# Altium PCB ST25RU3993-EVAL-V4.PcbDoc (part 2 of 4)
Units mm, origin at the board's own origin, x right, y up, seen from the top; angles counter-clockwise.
Board outline 76.25 x 96.25 mm, 6 copper layers (Top Layer, RF GND, Power, GND, Routing, Bottom GND), stack 1.022 mm thick; 319 components, 214 nets, 994 pads, 1429 vias.
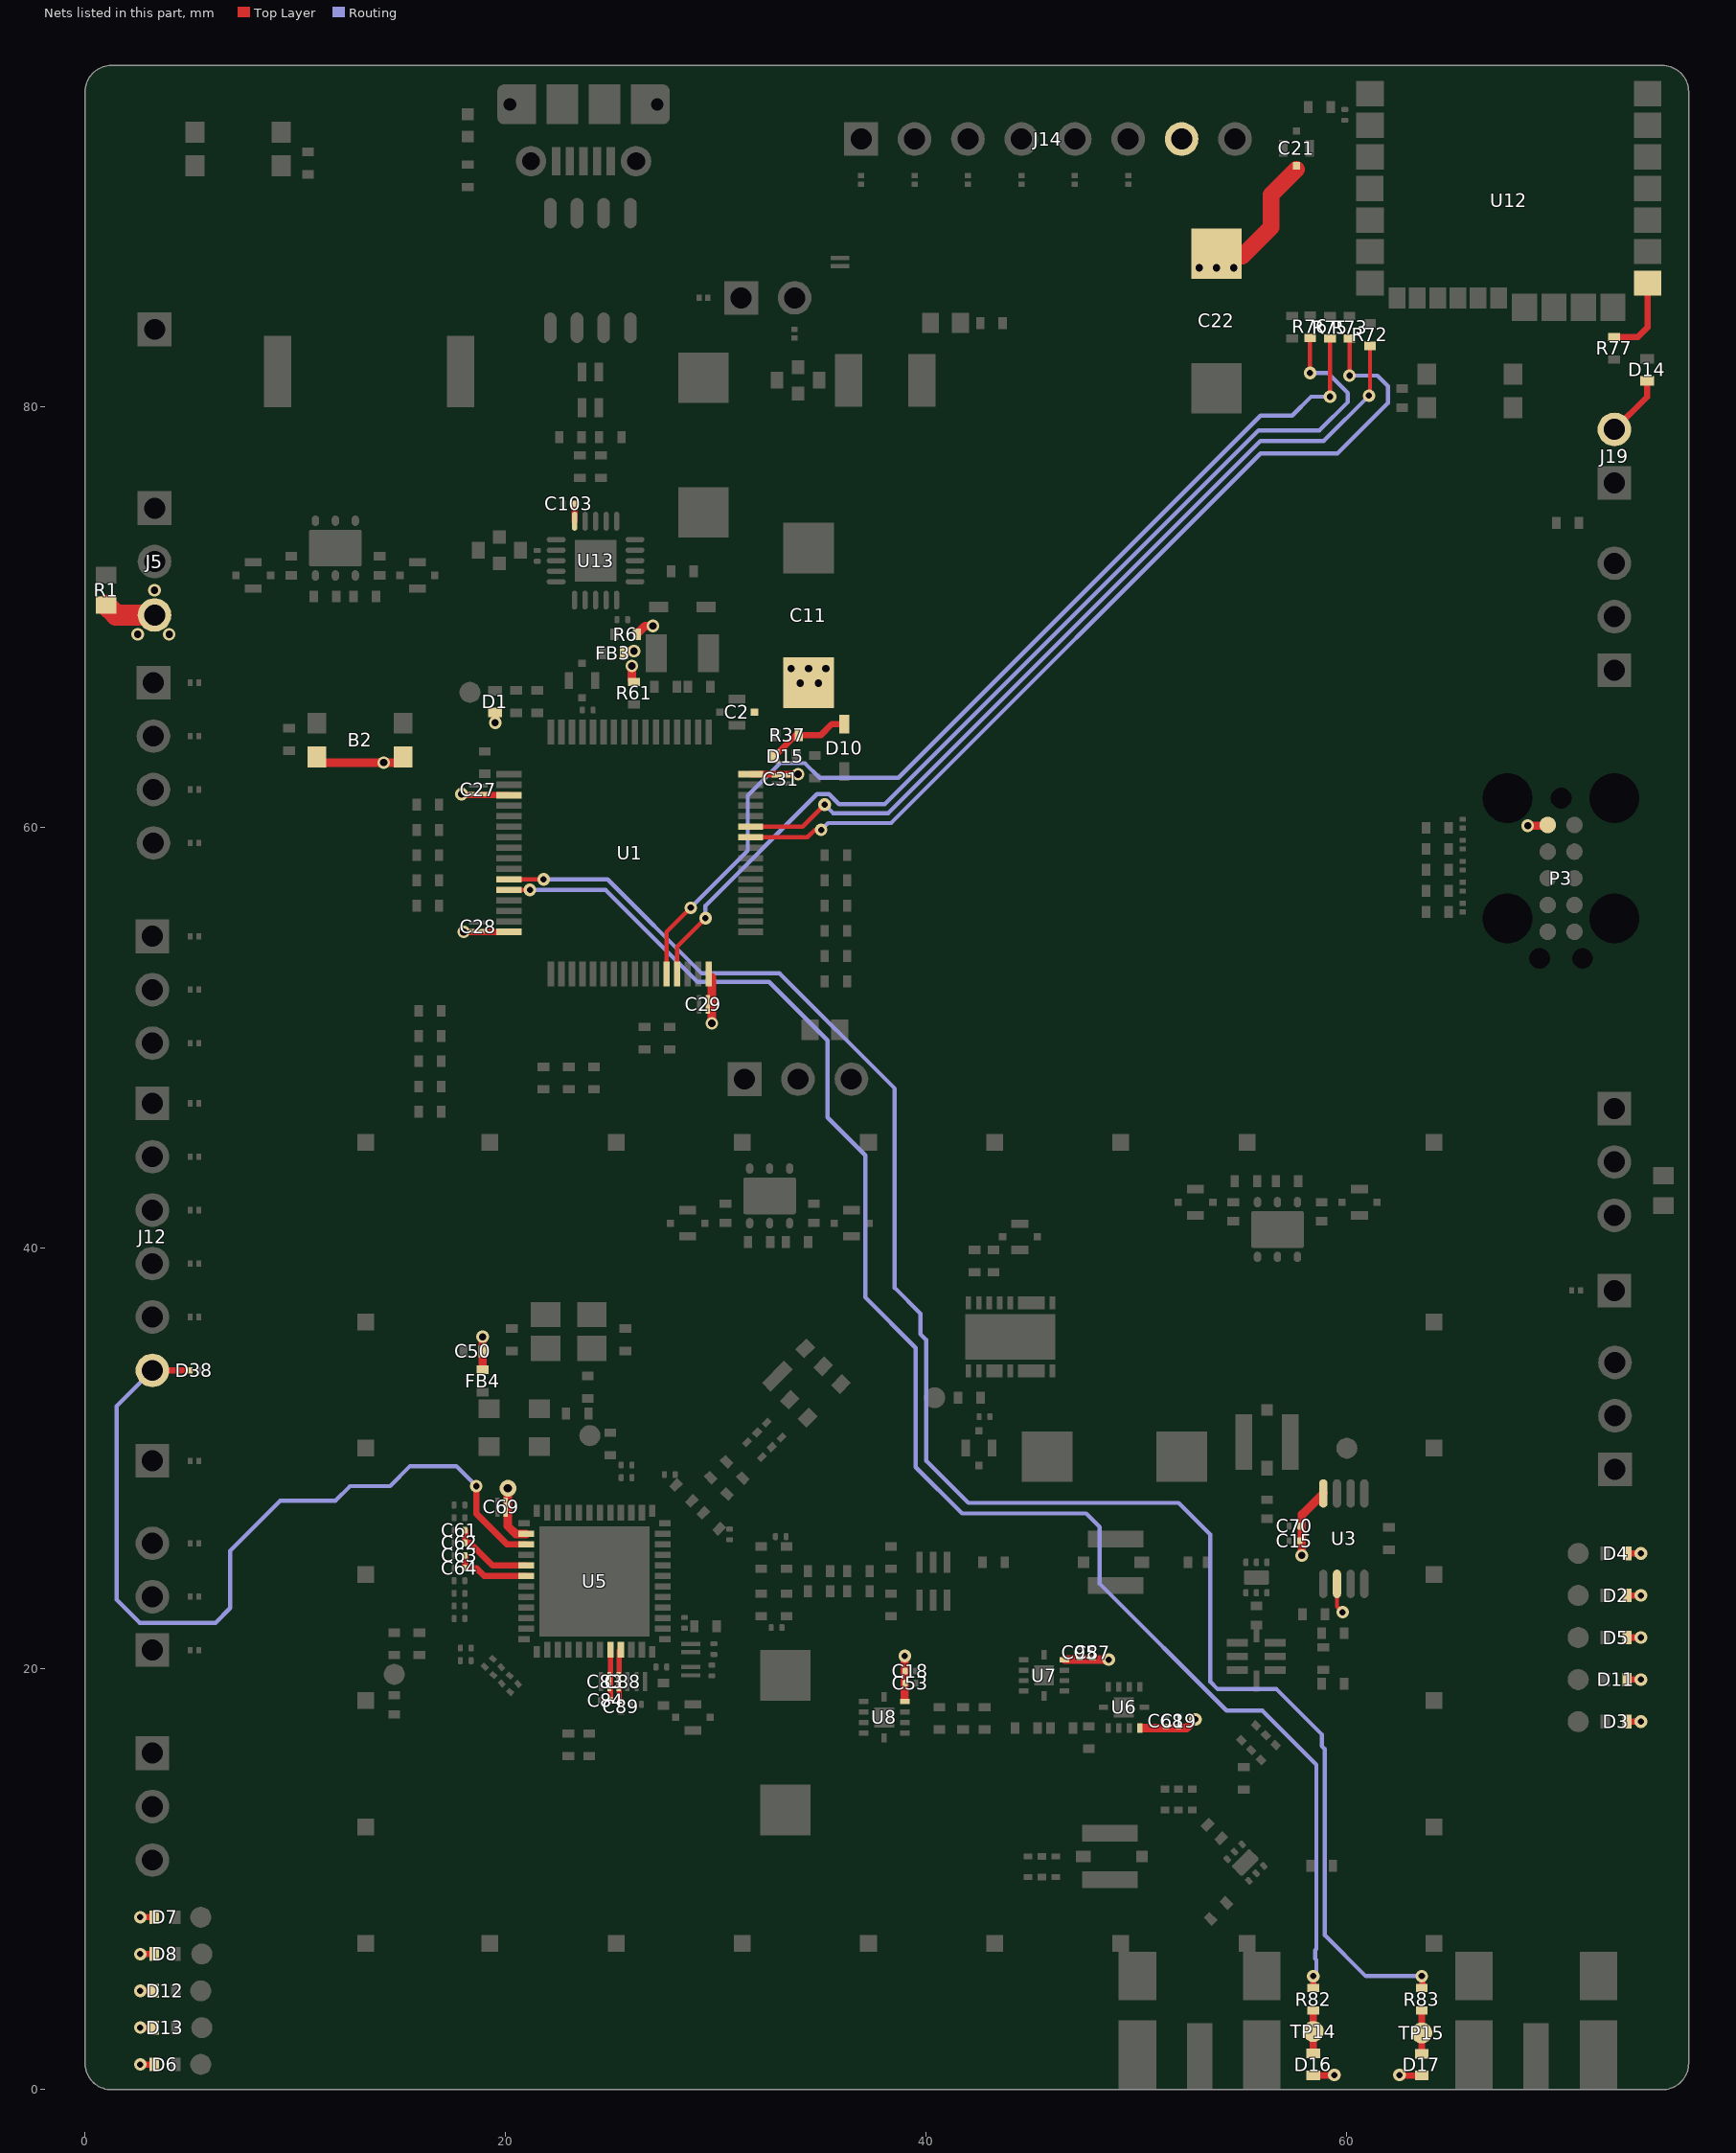
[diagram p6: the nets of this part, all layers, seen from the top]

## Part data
B1 B2 B3: library part SW-PUSH-CMS_BLACK_1, "Non-Open Push-Button 0.1A 24V", Contact Rating @ Voltage="0.05A @ 32VDC", Illumination Type, Color=-, Manufacturer="C&K Components", Manufacturer Part Number="KMR211NG LFS", Operating Force=120gf, Operating Temperature="-40°C ~ 85°C", Supplier Part Number 1=CKN10243DKR-ND
BZ1: library part PKMCS0909E4000-R1, "AUDIO PIEZO TRANSDUCER 12.5V SMD", Current - Supply=-, Frequency=4kHz, Manufacturer="Murata Electronics North America", Operating Mode="Single Tone", Operating Temperature="-40°C ~ 85°C", Supplier Part Number 1=490-9647-1-ND, Voltage - Rated=1.5V, Voltage Range="12.5V (Max)"
C1 C3: library part GRM1555C1H1R2WA01D, "CAP CER 1.2PF 50V NP0 0402", Capacitance=1.2pF, Manufacturer="Murata Electronics North America", Operating Temperature="-55°C ~ 125°C", Package / Case="0402 (1005 Metric)", Ratings=-, Supplier Part Number 1=490-6210-1-ND, Temperature Coefficient="C0G, NP0", Tolerance=±0.05pF, Voltage - Rated=50V
C2 C8 C16 C21 C39 C41 C43 C45 C47 C49 C91 C104: library part NFM18PS474R0J3D, "CAP FEEDTHRU 0.47UF 6.3V 0603", Capacitance=0.47µF, Current=2A, DC Resistance (DCR) (Max)="30 mOhm", ESR (Equivalent Series Resistance)="70 mOhm", Lifetime @ Temp.="1000 Hrs @ 105°C", Manufacturer="Murata Electronics North America", Operating Temperature="-55°C ~ 125°C", Package / Case="0603 (1608 Metric), 3 PC Pad", Ratings=-, Ripple Current - High Frequency="1A @ 100kHz", Supplier Part Number 1=490-6975-1-ND, Tolerance=±20%, Voltage - Rated=6.3V
C4 C5: library part GRM1555C1H150GA01D, "CAP CER 15PF 50V NP0 0402", Manufacturer="Murata Electronics North America", Operating Temperature="-55°C ~ 125°C", Package / Case="0402 (1005 Metric)", Ratings=-, Supplier Part Number 1=490-6201-1-ND, Temperature Coefficient="C0G, NP0", Tolerance=±2%, Voltage - Rated=50V
C6 C7: library part GJM1555C1H5R6CB01D, "CAP CER 5.6PF 50V NP0 0402", Capacitance=5.6pF, Frequency Max=960, Frequency Min=380, Frequency Range="380MHz to 960", Manufacturer="Murata Electronics North America", Manufacturer 2=RFMD, Manufacturer Part Number 2=RFPA0133, Operating Temperature="-55°C ~ 125°C", Operating Temperature Max=85, Operating Temperature Min=-40, Operating Temperature Range="-40°C to +85", Package / Case="0402 (1005 Metric)", Ratings=-, RF IC Case Style=QFN, Supplier Part Number 1=490-3103-1-ND, Supply Current=320, Supply Voltage Max=5, Supply Voltage Min=3, Supply Voltage Range="3V to 5V<!--FANDB--><div class{}\"features-and-benefits-container\"><div class{}\"features-and-benefits-description\"><span class{}\"features-benefits-value\">The RFPA0133 is a 3 to 5V high efficiency programmable gain Power Amplifier designed to offer saturated efficiency greater than 60% over a range of frequencies from 380 to 960MHz. The device is manufactured on an advanced Gallium Arsenide Heterojunction Bipolar Transistor (HBT) process.</span></div><div class{}\"features-and-benefits-list\"><ul class{}\"features-and-benefits-list-list\"><li class{}\"features-and-benefits-list-item\">0.5W CW Output power at 3.6V</li><li class{}\"features-and-benefits-list-item\">1W CW Output power at 5V</li><li class{}\"features-and-benefits-list-item\">32dB Small signal gain at 900", Temperature Coefficient="C0G, NP0", Tolerance=±0.25pF, Voltage - Rated=50V
C9 C10: library part GRM1555C2A4R7CA01D, "CAP CER 4.7PF 100V NP0 0402", Capacitance=4.7pF, ESR (Equivalent Series Resistance)="70 kOhm", Frequency=32.768kHz, Frequency Stability=-, Frequency Tolerance=±20ppm, Load Capacitance=12.5pF, Manufacturer="Murata Electronics North America", Manufacturer 2=NDK, Manufacturer Part Number 2=NX3215SA-32.768K-STD-MUA-8, Operating Mode=Fundamental, Operating Temperature="-55°C ~ 125°C", Package / Case="0402 (1005 Metric)", Supplier Part Number 1=490-7290-1-ND, Temperature Coefficient="C0G, NP0", Tolerance=±0.25pF, Voltage - Rated=100V
C11 C20 C22 C92: library part ECASD41C106M060K00, "CAP POLYMER 10UF 20% 16V SMD", Capacitance=10µF, ESR (Equivalent Series Resistance)="60 mOhm @ 100kHz", Lifetime @ Temp.="1000 Hrs @ 105°C", Manufacturer=Murata, Operating Temperature="-40°C ~ 105°C", Package / Case="2917 (7343 Metric)", Ripple Current=1A, Standard Package=3,000, Supplier Part Number 1=16705082, Tolerance=±20%, Voltage Rating=16V
C12 C14 C53 C57 C58 C60 C62 C64 C68 C70 C76 C95: library part GRM0335C1H121JA01D, "CAP CER 120PF 50V C0G/NP0 0201", Manufacturer="Murata Electronics North America", Operating Temperature="-55°C ~ 125°C", Package / Case="0201 (0603 Metric)", Ratings=-, Supplier Part Number 1=490-7221-1-ND, Temperature Coefficient="C0G, NP0", Tolerance=±5%, Voltage - Rated=50V
C13 C15 C18 C19 C24 C26 C30 C33 C52 C59 C61 C63 C66 C71 C73 C75 C78 C84 C85 C87 C89 C90 C105: library part GRM033R60J225ME15D, "CAP CER 2.2UF 6.3V X5R 0201", Capacitance=2.2µF, Manufacturer="Murata Electronics North America", Operating Temperature="-55°C ~ 85°C", Package / Case="0201 (0603 Metric)", Ratings=-, Supplier Part Number 1=490-13224-1-ND, Temperature Coefficient=X5R, Tolerance=±20%, Voltage - Rated=6.3V
C17: library part "GRM155R71H222KA01D (2)", "CAP CER 2.2NF 50V X7R 0402", Manufacturer="Murata Electronics North America", Manufacturer Part Number=GRM155R71H222KA01D, Operating Temperature="-55°C ~ 125°C", Package / Case="0402 (1005 Metric)", Ratings=-, Supplier Part Number 1=490-1305-1-ND, Temperature Coefficient=X7R, Tolerance=±10%, Voltage - Rated=50V
C23: library part ECASD41C685M070K00, "CAP ALUM POLY 6.8UF 20% 16V SMD", ESR (Equivalent Series Resistance)="70 mOhm", Lifetime @ Temp.="1000 Hrs @ 105°C", Manufacturer="Murata Electronics North America", Operating Temperature="-40°C ~ 105°C", Package / Case="2917 (7343 Metric)", Ripple Current - High Frequency="1A @ 100kHz", Ripple Current - Low Frequency=-, Supplier Part Number 1=490-5481-1-ND, Tolerance=±20%
C25 C50 C106: library part GRM155R71C104KA88D, "CAP CER 0.1UF 16V X7R 0402", Capacitance=0.10µF, Manufacturer="Murata Electronics North America", Operating Temperature="-55°C ~ 125°C", Package / Case="0402 (1005 Metric)", Ratings=-, Supplier Part Number 1=490-3261-1-ND, Temperature Coefficient=X7R, Tolerance=±10%, Voltage - Rated=16V
C27 C28 C29 C31 C67 C69 C77 C83 C86 C88 C98: library part LLL153C80J104ME01E, "CAP CER 0.1UF 6.3V X6S 0204", Capacitance @ Frequency=-, Manufacturer="Murata Electronics North America", Operating Temperature="-55°C ~ 105°C", Package / Case="0204 (0510 Metric)", Power - Peak Pulse=500W, Power Line Protection=Yes, Supplier Device Package=8-SO, Supplier Part Number 1=490-4310-1-ND, Temperature Coefficient=X6S, Tolerance=±20%, Voltage - Breakdown (Min)=6V, Voltage - Rated=6.3V, Voltage - Reverse Standoff (Typ)=5.25V
C32 C35 C36 C54 C65 C93 C94 C107 C108 C109 C112: library part GRM1555C1H820GA01J, "CAP CER 82PF 50V C0G/NP0 0402", Capacitance @ Frequency="0.4pF @ 200MHz ~ 3GHz", Current - Peak Pulse (10/1000µs)="1A (8/20µs)", Current Rating (Max)=250mA, DC Resistance (DCR) (Max)="1.1 Ohm", Impedance @ Frequency="1 kOhm @ 100MHz", Manufacturer="Murata Electronics North America", Operating Temperature="-55°C ~ 125°C", Package / Case="0402 (1005 Metric)", Power - Peak Pulse=40W, Power Line Protection=No, Ratings=-, Supplier Device Package=SOD-882T, Supplier Part Number 1=490-7760-1-ND, Temperature Coefficient="C0G, NP0", Tolerance=±2%, Voltage - Breakdown (Min)=6V, Voltage - Clamping (Max) @ Ipp=17V, Voltage - Rated=50V, Voltage - Reverse Standoff (Typ)=3V
C34 C72 C74: library part GRM0335C1H300GA01D, "CAP CER 30PF 50V C0G/NP0 0201", Manufacturer="Murata Electronics North America", Operating Temperature="-55°C ~ 125°C", Package / Case="0201 (0603 Metric)", Ratings=-, Supplier Part Number 1=490-14560-1-ND, Temperature Coefficient="C0G, NP0", Tolerance=±2%, Voltage - Rated=50V
C37: library part GRM1555C1H3R6BA01D, "CAP CER 3.6PF 50V C0G/NP0 0402", Manufacturer="Murata Electronics North America", Operating Temperature="-55°C ~ 125°C", Package / Case="0402 (1005 Metric)", Ratings=-, Supplier Part Number 1=490-8205-1-ND, Temperature Coefficient="C0G, NP0", Tolerance=±0.1pF, Voltage - Rated=50V
C38 C40 C42 C44 C46 C48: library part GRM155R60J225ME95D, "CAP CER 2.2UF 6.3V  X5R  0402", Manufacturer="Murata Electronics North America", Operating Temperature="-55°C ~ 85°C", Package / Case="0402 (1005 Metric)", Ratings=-, Supplier Part Number 1=490-13407-1-ND, Temperature Coefficient=X5R, Tolerance=±20%, Voltage - Rated=6.3V
C51: library part GRM155R6YA224KE01D, "CAP CER 0.22UF 35V X5R 0402", Manufacturer="Murata Electronics North America", Operating Temperature="-55°C ~ 85°C", Package / Case="0402 (1005 Metric)", Ratings=-, Supplier Part Number 1=490-10460-1-ND, Temperature Coefficient=X5R, Tolerance=±10%, Voltage - Rated=35V
C55: library part GRM1557U1A392JA01D, "CAP CER 3900PF 10V U2J 0402", Capacitance=3900pF, Manufacturer="Murata Electronics North America", Operating Temperature="-55°C ~ 125°C", Package / Case="0402 (1005 Metric)", Ratings=-, Supplier Part Number 1=490-10691-1-ND, Temperature Coefficient=U2J, Tolerance=±5%, Voltage - Rated=10V
C56: library part GRM1555C1H151FA01D, "CAP CER 150PF 50V NP0 0402", Manufacturer="Murata Electronics North America", Operating Temperature="-55°C ~ 125°C", Package / Case="0402 (1005 Metric)", Ratings=-, Supplier Part Number 1=490-8185-1-ND, Temperature Coefficient="C0G, NP0", Tolerance=±1%, Voltage - Rated=50V
C79 C80 C81 C82: library part GRM033R61E103KA12D, "CAP CER 10000PF 10V X7R 0201", Capacitance=10000pF, Manufacturer="Murata Electronics North America", Manufacturer Part Number=GRM033R71A103KA01D, Operating Temperature="-55°C ~ 125°C", Package / Case="0201 (0603 Metric)", Ratings=-, Supplier Part Number 1=490-3194-1-ND, Temperature Coefficient=X7R, Tolerance=±10%, Voltage - Rated=10V
C96 C99: library part NFM21PC105B1A3D, "CAP FEEDTHRU 1UF 20% 10V 0805", Capacitance=1µF, Current=4A, DC Resistance (DCR) (Max)="20 mOhm", Frequency="1.7GHz ~ 2.2GHz", Manufacturer="Murata Electronics North America", Operating Temperature="-40°C ~ 85°C", Package / Case="0805 (2012 Metric), 3 PC Pad", Power - Max=2W, Ratings=-, Supplier Device Package="0805 (2012 Metric)", Supplier Part Number 1=490-6980-1-ND, Tolerance=±20%, Voltage - Rated=10V
C97: library part GRM188R61A475KE15D, "CAP CER 4.7UF 10V X5R 0603", Manufacturer="Murata Electronics North America", Operating Temperature="-55°C ~ 85°C", Package / Case="0603 (1608 Metric)", Ratings=-, Supplier Part Number 1=490-10477-1-ND, Temperature Coefficient=X5R, Tolerance=±10%, Voltage - Rated=10V
C100: library part GRM1555C1H4R0CA01D, "CAP CER 4PF 50V C0G/NP0 0402", Manufacturer="Murata Electronics North America", Operating Temperature="-55°C ~ 125°C", Package / Case="0402 (1005 Metric)", Ratings=-, Supplier Part Number 1=490-5873-1-ND, Temperature Coefficient="C0G, NP0", Tolerance=±0.25pF, Voltage - Rated=50V
C101 C102: library part GRM1555C1H470FA01D, "CAP CER 47PF 50V NP0 0402", Manufacturer="Murata Electronics North America", Operating Temperature="-55°C ~ 125°C", Package / Case="0402 (1005 Metric)", Ratings=-, Supplier Part Number 1=490-6241-1-ND, Temperature Coefficient="C0G, NP0", Tolerance=±1%, Voltage - Rated=50V
C103: library part GRM033C80J104KE15D, "CAP CER 0.1UF 6.3V X6S 0201", Capacitance=0.10µF, Manufacturer="Murata Electronics North America", Operating Temperature="-55°C ~ 105°C", Package / Case="0201 (0603 Metric)", Ratings=-, Supplier Part Number 1=490-10390-1-ND, Temperature Coefficient=X6S, Tolerance=±10%, Voltage - Rated=6.3V
C110 C111: library part "GJM1555C1H110GB01D (2)", "CAP CER 11PF 50V C0G/NP0 0402", Manufacturer="Murata Electronics North America", Manufacturer Part Number=GJM1555C1H110GB01D, Operating Temperature="-55°C ~ 125°C", Package / Case="0402 (1005 Metric)", Ratings=-, Supplier Part Number 1=490-6072-1-ND, Temperature Coefficient="C0G, NP0", Tolerance=±2%, Voltage - Rated=50V
D1 D2 D3 D4 D5 D6 D7 D8 D11 D14 D16 D17: library part LNJ947W8CRA, "LED BLUE 0402 SMD", Color=Blue, Current - Test=5mA, Lens Color=-, Manufacturer="Panasonic Electronic Components", Millicandela Rating=18mcd, Package / Case="0402 (1005 Metric)", Supplier Part Number 1=LNJ947W8CRADKR-ND, Voltage - Forward (Vf) (Typ)=2.9V
D9 D10: "DIODE SCHOTTKY 10V 3A SOD323", Capacitance @ Vr, F=-, Current - Average Rectified (Io)="3A (DC)", Current - Reverse Leakage @ Vr="6µA @ 10V", Manufacturer=STMicroelectronics, Operating Temperature - Junction="150°C (Max)", Package / Case="SC-76, SOD-323", Supplier Device Package=SOD-323, Supplier Part Number 1=497-3707-1-ND, Voltage - DC Reverse (Vr) (Max)=10V, Voltage - Forward (Vf) (Max) @ If="580mV @ 1A"
D12 D13 D15: library part LNJ247W82RA, "LED RED 0402 SMD", Base Part Number=LNJ*47, Color=Red, Current - Test=5mA, Lens Color=-, Manufacturer="Panasonic Electronic Components", Millicandela Rating=16mcd, Package / Case="0402 (1005 Metric)", Supplier Device Package="1005 Type", Supplier Part Number 1=LNJ247W82RACT-ND, Voltage - Forward (Vf) (Typ)=1.95V
D20 D21 D22 D23 D24 D25 D26 D27 D28 D29 D30 D31 D32 D33 D34 D35 D36 D37 D38 D39 D40 D41 D42 D43 D44 D45 D47 D48 D49 D50 D52: library part ESDAXLC6-1BU2, "TVS DIODE 3VWM 17VC ST0201", Capacitance @ Frequency="0.4pF @ 200MHz ~ 3GHz", Current - Peak Pulse (10/1000µs)="1A (8/20µs)", Manufacturer=STMicroelectronics, Operating Temperature="-40°C ~ 150°C (TJ)", Package / Case="0201 (0603 Metric)", Power (Watts)="0.1W, 1/10W", Power - Peak Pulse=40W, Power Line Protection=No, Supplier Device Package=ST0201, Supplier Part Number 1=497-13414-1-ND, Temperature Coefficient=±100ppm/°C, Tolerance=±1%, Voltage - Breakdown (Min)=6V, Voltage - Clamping (Max) @ Ipp=17V, Voltage - Reverse Standoff (Typ)=3V
FB1: library part BLM15PX331SN1D, "FERRITE BEAD 330 OHM 0402 1LN", Current Rating (Max)=1.2A, DC Resistance (DCR) (Max)="150 mOhm", Manufacturer="Murata Electronics North America", Operating Temperature="-55°C ~ 125°C", Package / Case="0402 (1005 Metric)", Ratings=-, Supplier Part Number 1=490-11022-1-ND
FB2 FB3 FB4 FB5: library part BLM15HG102SN1D, "FERRITE BEAD 1 KOHM 0402 1LN", Current Rating (Max)=250mA, DC Resistance (DCR) (Max)="1.1 Ohm", Impedance @ Frequency="1 kOhm @ 100MHz", Manufacturer="Murata Electronics North America", Operating Temperature="-55°C ~ 125°C", Package / Case="0402 (1005 Metric)", Ratings=-, Supplier Part Number 1=490-3999-1-ND
FB7: library part NFZ32BW310HN11L, "FERRITE BEAD 31 OHM 2SMD 1LN", Current Rating (Max)=1.2A, DC Resistance (DCR) (Max)="186 mOhm", Manufacturer="Murata Electronics North America", Operating Temperature="-40°C ~ 125°C", Package / Case="2-SMD, Flat Lead", Ratings=-, Supplier Part Number 1=490-9317-1-ND
J1: library part MS-156HF_SAW, "CONN COAX JACK STR 50 OHM SMD", Capacitance=2.2µF, Current=4A, DC Resistance (DCR)="1.25 Ohm Max", DC Resistance (DCR) (Max)="10 mOhm", Dielectric Material="Polyamide (PA), Nylon 6T", Frequency="700MHz ~ 1GHz", Frequency - Max=6GHz, Housing Color=Gold, Manufacturer="Hirose Electric Co Ltd", Manufacturer 2=Anaren, Manufacturer Part Number=MS-156HF(01), Manufacturer Part Number 2=DC0710J5010AHF, Operating Temperature="-40°C ~ 85°C", Package / Case="0805 (2012 Metric)", Power - Max=2W, Ratings=-, Supplier Device Package=0805, Supplier Part Number 1=H11669-ND, Tolerance=±20%, Voltage - Rated=10V
J2 J5 J8 J10 J13 J15 J20 J21: library part Pin_Header_x3, "Pin_Header_x3", Current Rating=3A, Insulation Color=Black, Manufacturer="Wurth Electronics Inc.", Manufacturer Part Number=61300311121, Material Flammability Rating="UL94 V-0", Operating Temperature="-40°C ~ 125°C", Supplier Part Number 1=732-5316-ND, Voltage Rating=250V
J3 J6 J9: library part MS-156HF, "CONN COAX JACK STR 50 OHM SMD", Dielectric Material="Polyamide (PA), Nylon 6T", Frequency="700MHz ~ 1GHz", Frequency - Max=6GHz, Housing Color=Gold, Manufacturer="Hirose Electric Co Ltd", Manufacturer 2=Anaren, Manufacturer Part Number=MS-156HF(01), Manufacturer Part Number 2=DC0710J5010AHF, Operating Temperature="-40°C ~ 85°C", Package / Case="0805 (2012 Metric)", Power - Max=2W, Supplier Device Package=0805, Supplier Part Number 1=H11669-ND, Voltage Rating=-
J4 J11 J16: library part Pin_Header_x1, "Pin_Header_x1", Current Rating=3A, Insulation Color=Black, Manufacturer="Wurth Electronics Inc.", Manufacturer Part Number=61300211121, Material Flammability Rating="UL94 V-0", Operating Temperature="-40°C ~ 125°C", Supplier Part Number 1=732-5315-ND, Voltage Rating=250V
J7: library part Pin_Header_x4, "Pin_Header_x4", Current Rating="Varies by Wire Gauge", Insulation Color=Natural, Manufacturer="TE Connectivity AMP Connectors", Manufacturer Part Number=3-644456-4, Material Flammability Rating="UL94 V-0", Operating Temperature="-55°C ~ 105°C", Supplier Part Number 1=A31114-ND, Voltage Rating=250VAC
J12: library part Pin_Header_x6, "Pin_Header_x6", Color=Natural, Manufacturer="Amphenol FCI", Manufacturer Part Number=10114828-10102LF, Supplier Part Number 1=609-4387-1-ND
J14: library part Pin_Header_x8, "Pin_Header_x8", Current Rating="Varies by Wire Gauge", Insulation Color=Natural, Manufacturer="TE Connectivity AMP Connectors", Manufacturer Part Number=3-644456-8, Material Flammability Rating="UL94 V-0", Operating Temperature="-55°C ~ 105°C", Supplier Part Number 1=A31118-ND, Voltage Rating=250VAC
J19: library part Jumper2_THMD, Current Rating=-, Insulation Color=Black, Manufacturer="Amphenol FCI", Manufacturer Part Number=77311-118-02LF, Material Flammability Rating="UL94 V-0", Supplier Part Number 1=609-4434-ND
L1 L2 L3 L4: library part LQW15AN30NG00D, "FIXED IND 30NH 270MA 580 MOHM", Current - Saturation=-, Current Rating=270mA, DC Resistance (DCR)="580 mOhm Max", Frequency - Self Resonant=3.3GHz, Frequency - Test=100MHz, Manufacturer="Murata Electronics North America", Operating Temperature="-55°C ~ 125°C", Package / Case="0402 (1005 Metric)", Q @ Freq="25 @ 250MHz", Supplier Part Number 1=490-6802-1-ND, Tolerance=±2%
L10 L15: library part LQW15AN3N6C10D, "FIXED IND 3.6NH 900MA 40 MOHM", Current - Saturation=-, Current Rating=900mA, DC Resistance (DCR)="40 mOhm Max", Frequency - Self Resonant=9.5GHz, Frequency - Test=100MHz, Inductance=3.6nH, Manufacturer="Murata Electronics North America", Operating Temperature="-55°C ~ 125°C", Package / Case="0402 (1005 Metric)", Q @ Freq="30 @ 250MHz", Supplier Part Number 1=490-6811-1-ND, Tolerance=±0.2nH
L11: library part LQW15AN6N8G00D, "FIXED IND 6.8NH 700MA 90 MOHM", DC Resistance (DCR)="90 mOhm Max", Manufacturer="Murata Electronics North America", Operating Temperature="-55°C ~ 125°C", Package / Case=Nonstandard, Q @ Freq="25 @ 250MHz", Ratings=-, Supplier Device Package="0402 (1005 Metric)", Supplier Part Number 1=490-6840-1-ND, Tolerance=±2%
L12: library part LQW15AN5N6C10D, "Inductor RF Chip Wirewound 5.6nH 0.2nH 100MHz 30Q-Factor 800mA 51mOhm DCR 0402 T/R", Case/Package=0402, Case Code (Metric)=1005, Current Rating=800mA, DC Resistance (DCR)=51mR, Inductance=5.6nh, Manufacturer=Murata, Max Operating Temperature=125°C, Min Operating Temperature=-55°C, Package Quantity=1, Self Resonant Frequency=8GHz, Supplier Part Number 1=490-6833-6-ND, Test Frequency=100MHz
P1: "Micro USB Connector", Current Rating="1A, 1.8A", Insulation Color=Black, Manufacturer="Molex, LLC", Manufacturer Part Number=1050170001, Material Flammability Rating="UL94 V-0", Operating Temperature="-30°C ~ 85°C", Supplier Part Number 1=WM1399CT-ND, Voltage - Rated=30VAC
P2: "Header, 2-Pin, Right Angle"
P4 P5: library part 903-723J-51S, "CONN SMB JACK STR 50OHM EDGE MNT", Dielectric Material="Polytetrafluoroethylene (PTFE)", Housing Color=Silver, Manufacturer="Amphenol RF Division", Operating Temperature="-65°C ~ 165°C", Supplier Part Number 1=903-723J-51S-ND
R1 R2 R3: library part RC0603JR-070RL, "RES SMD 0.0OHM JUMPER 1/10W 0603", Manufacturer=Yageo, Supplier Part Number 1=311-0.0GRCT-ND
R4 R5 R14 R15 R17 R18 R19 R42 R46 R50 R51 R52 R53 R64 R65 R66 R77 R81 R82 R83: library part RC0402JR-07220RL, "RES SMD 220 OHM 5% 1/16W 0402", Manufacturer=Yageo, Operating Temperature="-55°C ~ 155°C", Package / Case="0402 (1005 Metric)", Power (Watts)="0.063W, 1/16W", Supplier Device Package=0402, Supplier Part Number 1=311-220JRCT-ND, Temperature Coefficient=±100ppm/°C, Tolerance=±5%
R6 R7 R8 R9 R10 R11 R12 R13 R20 R34 R36 R37 R38 R39 R40 R43 R54 R55 R56 R57 R58 R72 R73 R75 R76 R89: library part RC0402JR-070RL, "RES SMD 0.0OHM JUMPER 1/16W 0402", Manufacturer=Yageo, Operating Temperature="-55°C ~ 155°C", Package / Case="0402 (1005 Metric)", Power (Watts)="0.063W, 1/16W", Resistance (Ohms)=0.0, Supplier Device Package=0402, Supplier Part Number 1=311-0.0JRDKR-ND, Temperature Coefficient=-, Tolerance=Jumper
R16 R27 R29 R31 R61: library part RC0402FR-0710KL, "RES SMD 10K OHM 1% 1/16W 0402", Manufacturer=Yageo, Operating Temperature="-55°C ~ 155°C", Package / Case="0402 (1005 Metric)", Power (Watts)="0.063W, 1/16W", Supplier Device Package=0402, Supplier Part Number 1=311-10.0KLRCT-ND, Temperature Coefficient=±100ppm/°C, Tolerance=±1%
R21 R35: library part RC0402FR-07100RL, "RES SMD 100 OHM 1% 1/16W 0402", Manufacturer=Yageo, Operating Temperature="-55°C ~ 155°C", Package / Case="0402 (1005 Metric)", Power (Watts)="0.063W, 1/16W", Resistance (Ohms)=100, Supplier Device Package=0402, Supplier Part Number 1=311-100LRCT-ND, Temperature Coefficient=±100ppm/°C, Tolerance=±1%
R22: library part RC0402FR-0751R1L, "RES SMD 51.1 OHM 1% 1/16W 0402", Manufacturer=Yageo, Operating Temperature="-55°C ~ 155°C", Package / Case="0402 (1005 Metric)", Power (Watts)="0.063W, 1/16W", Supplier Device Package=0402, Supplier Part Number 1=311-51.1LRCT-ND, Temperature Coefficient=±100ppm/°C, Tolerance=±1%
R23: library part ERJ2RKF52R3X, "RES SMD 52R3 1% 0.1W 0402", Manufacturer="Panasonic Electronic Components", Manufacturer Part Number=ERJ-2RKF52R3X, Operating Temperature="-55°C ~ 155°C", Package / Case="0402 (1005 Metric)", Power (Watts)="0.1W, 1/10W", Supplier Device Package=0402, Supplier Part Number 1=P52.3LCT-ND, Temperature Coefficient=±100ppm/°C, Tolerance=±1%
R24: library part RC0402FR-07249RL, "RES SMD 249 OHM 1% 1/16W 0402", Manufacturer=Yageo, Operating Temperature="-55°C ~ 155°C", Package / Case="0402 (1005 Metric)", Power (Watts)="0.063W, 1/16W", Supplier Device Package=0402, Supplier Part Number 1=311-249LRCT-ND, Temperature Coefficient=±100ppm/°C, Tolerance=±1%
R25 R45: library part RC0402FR-0762RL, "RES SMD 62 OHM 1% 1/16W 0402", Manufacturer=Yageo, Operating Temperature="-55°C ~ 155°C", Package / Case="0402 (1005 Metric)", Power (Watts)="0.063W, 1/16W", Supplier Device Package=0402, Supplier Part Number 1=311-62.0LRCT-ND, Temperature Coefficient=±100ppm/°C, Tolerance=±1%
R26: library part ERJ-2RKF75R0X, "Res Thick Film 0402 75 Ohm 1% 0.1W(1/10W) ±100ppm/C Molded SMD Automotive Punched T/R", Case/Package=0402, Case Code (Metric)=1005, Manufacturer=Panasonic, Max Operating Temperature=155°C, Max Power Dissipation=100mW, Min Operating Temperature=-55°C, Package Quantity=1, Supplier Part Number 1=P75.0LDKR-ND, Temperature Coefficient=100ppm/°C, Tolerance=1%, Voltage Rating=50V
R28: library part RC0402FR-0735K7L, "RES SMD 35.7K OHM 1% 1/16W 0402", Manufacturer=Yageo, Operating Temperature="-55°C ~ 155°C", Package / Case="0402 (1005 Metric)", Power (Watts)="0.063W, 1/16W", Supplier Device Package=0402, Supplier Part Number 1=311-35.7KLRCT-ND, Temperature Coefficient=±100ppm/°C, Tolerance=±1%
R30: library part ERJ-2RKF4222X, "RES SMD 42.2K OHM 1% 1/10W 0402", Manufacturer="Panasonic Electronic Components", Operating Temperature="-55°C ~ 155°C", Package / Case="0402 (1005 Metric)", Power (Watts)="0.1W, 1/10W", Supplier Device Package=0402, Supplier Part Number 1=P42.2KLCT-ND, Temperature Coefficient=±100ppm/°C, Tolerance=±1%
R33: library part ERJ-2GEJ153X, "RES SMD 15K OHM 5% 1/10W 0402", Manufacturer="Panasonic Electronic Components", Operating Temperature="-55°C ~ 155°C", Package / Case="0402 (1005 Metric)", Power (Watts)="0.1W, 1/10W", Supplier Device Package=0402, Supplier Part Number 1=P15KJCT-ND, Temperature Coefficient=±200ppm/°C, Tolerance=±5%
R41 R47: library part RC0402FR-0727RL, "RES SMD 27 OHM 1% 1/16W 0402", Manufacturer=Yageo, Operating Temperature="-55°C ~ 155°C", Package / Case="0402 (1005 Metric)", Power (Watts)="0.063W, 1/16W", Resistance (Ohms)=27, Supplier Device Package=0402, Supplier Part Number 1=YAG3086CT-ND, Temperature Coefficient=±100ppm/°C, Tolerance=±1%
R44: library part RC0402FR-0731K6L, "RES SMD 31.6K OHM 1% 1/16W 0402", Manufacturer=Yageo, Operating Temperature="-55°C ~ 155°C", Package / Case="0402 (1005 Metric)", Power (Watts)="0.063W, 1/16W", Resistance (Ohms)=31.6k, Supplier Device Package=0402, Supplier Part Number 1=YAG3115CT-ND, Temperature Coefficient=±100ppm/°C, Tolerance=±1%
R74 R78: library part RC0402FR-0710KL, "RES SMD 10K OHM 1% 1/16W 0402", Manufacturer=Yageo, Operating Temperature="-55°C ~ 155°C", Package / Case="0402 (1005 Metric)", Power (Watts)="0.063W, 1/16W", Resistance (Ohms)=10k, Supplier Device Package=0402, Supplier Part Number 1=311-10.0KLRCT-ND, Temperature Coefficient=±100ppm/°C, Tolerance=±1%
R86: library part RC0402JR-0720RL, "RES SMD 20 OHM 5% 1/16W 0402", Frequency="915MHz Center", Manufacturer=Yageo, Manufacturer 2="Johanson Technology Inc.", Manufacturer Part Number 2=0915LP15B026E, Operating Temperature="-55°C ~ 155°C", Package / Case="0402 (1005 Metric)", Power (Watts)="0.063W, 1/16W", Resistance (Ohms)=20, Supplier Device Package=0402, Supplier Part Number 1=311-20JRCT-ND, Temperature Coefficient=±100ppm/°C, Tolerance=±5%
S1 S2: library part SKY13431-374LF, "IC SWITCH SP2T", Frequency - Lower=500MHz, Insertion Loss @ Frequency="0.8dB @ 5.8GHz", Isolation @ Frequency="20dB @ 5.8GHz (typ)", Manufacturer="Skyworks Solutions Inc.", Operating Temperature="-40°C ~ 85°C", Package / Case="6-XFDFN Exposed Pad", Supplier Device Package="6-DFN (1.5x1.5)", Supplier Part Number 1=863-1651-1-ND, Voltage - Supply="2.5 V ~ 5 V"
SHIELD1: library part 2118732-2, "RF Shield 51.1 x 38.4 x 6.5", Manufacturer="TE Connectivity AMP Connectors", Supplier Part Number 1=A126160TR-ND
T1: library part 0900LP15B0063, "FILTER LOWPASS 863-960MHZ", Manufacturer="Johanson Technology Inc.", Manufacturer Part Number=0900LP15B0063E, Supplier Part Number 1=712-1635-1-ND
T2: library part DC1722J5020AHF, "COUPLER 20DB 1700-2200MHZ 0805", Frequency="1.7GHz ~ 2.2GHz", Manufacturer=Anaren, Package / Case="0805 (2012 Metric)", Power - Max=2W, Supplier Part Number 1=1173-1088-1-ND
T3: library part "1:1 BALUN 900MHZ - 0900BL15C050", "1:1 BALUN- 900MHZ 50/50 Ohm", Frequency Range="800 ~ 1000MHz", Manufacturer="Johanson Technology Inc", Manufacturer Part Number=0900BL15C050E, Package / Case="0805 (2012 Metric)", Supplier Part Number 1=712-1022-1-ND
T4: library part DC0710J5010AHF, "Directional Coupler", Frequency="700MHz ~ 1GHz", Manufacturer=Anaren, Package / Case="0805 (2012 Metric)", Power - Max=2W, Supplier Device Package=0805, Supplier Part Number 1=1173-1084-1-ND
T5 T6: library part BD0810J50100AHF, "XFRMR BALUN RF 800-1000MHZ 0805", Frequency Range="800MHz ~ 1GHz", Manufacturer=Anaren, Package / Case="0805 (2012 Metric)", Supplier Part Number 1=1173-1056-2-ND
T8: "CHOKE COM MODE 90 OHM .37A SMD", Current Rating (Max)=370mA, DC Resistance (DCR) (Max)="300 mOhm", Manufacturer="Wurth Electronics Inc.", Operating Temperature="-40°C ~ 125°C", Package / Case="Horizontal, 4 PC Pad", Ratings=-, Supplier Part Number 1=732-3198-1-ND, Voltage Rating - DC=50V
U1: "IC MCU 32BIT 1MB FLASH 64LQFP", Manufacturer=STMicroelectronics, Operating Temperature="-40°C ~ 85°C (TA)", Package / Case=64-LQFP, Supplier Device Package="64-LQFP (10x10)", Supplier Part Number 1=497-15877-ND, Voltage - Supply (Vcc/Vdd)="1.71 V ~ 3.6 V"
U2: "699 – 960 MHz 2-stage Power Amplifier", Manufacturer=Qorvo, Supplier Part Number 1=772-TQP9107
U3: library part MAX4003EUA+T, "IC LOG AMP RF DETECT 45DB 8-MSOP", Frequency="100MHz ~ 2.5GHz", Manufacturer="Maxim Integrated", Package / Case="8-TSSOP, 8-MSOP (0.118\", 3.00mm Width)", Supplier Device Package=8-uMAX, Supplier Part Number 1=MAX4003EUA+TCT-ND, Voltage - Supply="2.7 V ~ 5 V"
U4: library part TXETDCSANF-20.000000, "OSC TCXO 20.0000MHZ CLP SW SMD", Current - Supply (Disable) (Max)=-, Current - Supply (Max)=2mA, Frequency Stability=±2.5ppm, Manufacturer=Taitien, Operating Temperature="-20°C ~ 70°C", Package / Case="4-SMD, No Lead", Supplier Part Number 1=1664-1275-1-ND, Voltage - Supply="2.8 V ~ 3.3 V"
U5: "UHF EPC CLASS1 GEN2 READER", Frequency="860MHz ~ 960MHz", Manufacturer="ST Microelectronics", Manufacturer Part Number=ST25RU3993-BQFT, Operating Temperature=-, Package / Case="48-VFQFN Exposed Pad", Supplier Device Package="48-QFN (7x7)", Supplier Part Number 1=AS3993-BQFTTR-ND, Voltage - Supply="2.7 V ~ 3.6 V"
U6 U7 U8: "IC RF DTC 100-3000MHZ 10QFN", Frequency="100MHz ~ 3GHz", Frequency - Lower=500MHz, Insertion Loss @ Frequency="0.8dB @ 5.8GHz", Isolation @ Frequency="20dB @ 5.8GHz (typ)", Manufacturer="Peregrine Semiconductor", Operating Temperature="-40°C ~ 85°C", Package / Case="10-UFQFN Exposed Pad", Supplier Device Package="10-QFN (2x2)", Supplier Part Number 1=1046-1079-1-ND, Voltage - Supply="2.5 V ~ 5 V"
U9 U10 U11: "IC REG LDO ADJ 1A 6DFN", Current - Limit (Min)=-, Current - Output=1A, Manufacturer=STMicroelectronics, Operating Temperature="-40°C ~ 125°C", Package / Case="6-VDFN Exposed Pad", Supplier Device Package="6-DFN (3x3)", Supplier Part Number 1=497-11013-6-ND, Voltage - Dropout (Typical)="0.2V @ 1A", Voltage - Input="1.5 V ~ 5.5 V", Voltage - Output="0.8 V ~ 4.5 V"
U12: library part SPBT3, "SPBT3.0DP2 BLUETOOTH 3.0", Manufacturer=STMICROELECTRONICS, Manufacturer Part Number=SPBT3.0DP2, Silicon Manufacturer=STMicroelectronics, Supplier Part Number 1=497-17120-ND
U13: "IC USB SERIAL FULL UART 20QFN", Current - Supply=8mA, Manufacturer="FTDI, Future Technology Devices International Ltd", Operating Temperature="-40°C ~ 85°C", Package / Case="20-WFQFN Exposed Pad", Supplier Device Package="20-QFN (4x4)", Supplier Part Number 1=768-1128-1-ND, Voltage - Supply="3.3 V ~ 5 V"
U14: library part USB6B1RL, "TVS DIODE 5.25VWM 8SOIC", Capacitance @ Frequency=-, Manufacturer=STMicroelectronics, Operating Temperature="-40°C ~ 85°C (TA)", Package / Case="8-SOIC (0.154\", 3.90mm Width)", Power - Peak Pulse=500W, Power Line Protection=Yes, Supplier Device Package=8-SO, Supplier Part Number 1=497-3281-1-ND, Voltage - Breakdown (Min)=6V, Voltage - Reverse Standoff (Typ)=5.25V
X1: "CRYSTAL 32.7680KHZ 6PF SMD", ESR (Equivalent Series Resistance)="70 kOhm", Frequency=32.768kHz, Frequency Stability=-, Frequency Tolerance=±20ppm, Load Capacitance=6pF, Manufacturer="NDK America, Inc.", Operating Mode=Fundamental, Operating Temperature="-40°C ~ 85°C", Package / Case="2-SMD, No Lead", Supplier Part Number 1=644-1171-1-ND
X3: library part NX3225SA-20.000000MHZ-B2, "CRYSTAL 20.0000MHZ 7.2PF SMD", ESR (Equivalent Series Resistance)="80 Ohm", Frequency=20MHz, Frequency Stability=±15ppm, Frequency Tolerance=±10ppm, Load Capacitance=7.2pF, Manufacturer=NDK, Operating Mode=Fundamental, Operating Temperature="-30°C ~ 85°C", Package / Case="4-SMD, No Lead", Ratings=-, Supplier Part Number 1=644-1098-1-ND

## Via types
v1: diameter 0.6, hole 0.3, Top Layer to Bottom GND, tented both sides, 407 vias
v2: diameter 0.35, hole 0.35, Top Layer to Bottom GND, tented both sides, 245 vias
v3: diameter 0.61, hole 0.3, Top Layer to Bottom GND, tented both sides, 240 vias
v4: diameter 0.3, hole 0.3, Top Layer to Bottom GND, tented both sides, 105 vias
v5: diameter 0.4, hole 0.3, Top Layer to Bottom GND, tented both sides, 93 vias
v6: diameter 0.6/0.6/0.6/0.6/0.6/0.6 (per signal layer), hole 0.35, Top Layer to Bottom GND, tented both sides, 92 vias
v7: diameter 0.6, hole 0.35, Top Layer to Bottom GND, tented both sides, 71 vias
v8: diameter 0.2, hole 0.2, Top Layer to Bottom GND, tented both sides, 60 vias
v9: diameter 0.4, hole 0.2, Top Layer to Bottom GND, 45 vias
v10: diameter 0.6, hole 0.35, Top Layer to Bottom GND, 16 vias
v11: diameter 0.66, hole 0.33, Top Layer to Bottom GND, tented both sides, 16 vias
v12: diameter 0.35, hole 0.3, Top Layer to Bottom GND, tented both sides, 10 vias
v13: diameter 0.4, hole 0.4, Top Layer to Bottom GND, tented both sides, 6 vias
v14: diameter 1.8/2.51/2.51/2.51/2.51/2.51 (per signal layer), hole 1.71, Top Layer to Bottom GND, 6 vias
v15: diameter 0.5, hole 0.2, Top Layer to Bottom GND, 4 vias
v16: diameter 0.6, hole 0.3, Top Layer to Bottom GND, tented bottom, 4 vias
v17: diameter 0.5, hole 0.3, Top Layer to Bottom GND, tented both sides, 2 vias
v18: diameter 1.8/1.8/1.8/1.8/1.8/2.51 (per signal layer), hole 1.71, Top Layer to Bottom GND, 2 vias
v19: diameter 0.6, hole 0.2, Top Layer to Bottom GND, tented both sides, 2 vias
v20: diameter 0.4, hole 0.2, Top Layer to Bottom GND, tented both sides, 2 vias
v21: diameter 0.8, hole 0.4, Top Layer to Bottom GND, tented both sides, 1 vias

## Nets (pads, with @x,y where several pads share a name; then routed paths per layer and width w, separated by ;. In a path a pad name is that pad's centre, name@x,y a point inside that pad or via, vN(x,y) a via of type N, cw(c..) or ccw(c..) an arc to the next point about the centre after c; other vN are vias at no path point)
3V3: B2.1 B2.4 C2.1 C11.1 C15.1 C18.1 C19.1 C21.1 C22.1 C27.1 C28.1 C29.1 C31.1 C50.1 C53.1 C68.1 C69.1 C70.1 C87.1 C95.1 D1.1 D2.1 D3.1 D4.1 D5.1 D6.1 D7.1 D8.1 D11.1 D12.1 D13.1 D14.1 D16.1 D17.1 FB3.1 FB4.1 J5.3 J14.7 J19.2 P3.1 R1.1 R6.1 R61.1 U1.19 U1.32 U1.48 U1.64 U3.2 U3.8 U5.38 U6.4 U7.4 U8.4 | length 53.7
  Top Layer w0.2: U3.2@59.529,24.05 59.529,22.971 v1(59.8,22.7)
  Top Layer w0.3: v1(2.62,1.2) D6.1@3.28,1.2 ; v1(2.62,2.95) D13.1@3.28,2.95 ; v1(2.62,4.7) D12.1@3.28,4.7 ; v1(2.62,6.45) D8.1@3.28,6.45 ; v1(2.62,8.2) D7.1@3.28,8.2 ; v7(17.9,61.6) 17.9,61.55 U1.19@20.15,61.55 ; v7(18,55.05) U1.32@20.15,55.05 ; U1.64@31.65,62.55 v7(33.9,62.55) ; D16.1@58.4,0.68 59.38,0.68 v1(59.4,0.7) ; v1(62.5,0.7) 62.527,0.673 D17.1@63.561,0.673 ; J19.2@72.725,78.94 74.275,80.49 D14.1@74.275,81.255 ; D3.1@73.32,17.5 v1(73.98,17.5) ; D11.1@73.32,19.5 v1(73.98,19.5) ; D5.1@73.32,21.5 v1(73.98,21.5) ; D2.1@73.32,23.5 v1(73.98,23.5) ; D4.1@73.32,25.5 v1(73.98,25.5)
  Top Layer w0.4: B2.4@11.025,63.375 11.3,63.1 v7(14.2,63.1) 14.85,63.1 B2.1@15.125,63.375 ; FB4.1@18.9,34.233 C50.1@18.9,35.1 v7(18.9,35.8) ; v7(19.5,65) D1.1@19.5,65.48 ; v21(20.1,28.6) 20.1,26.8 20.475,26.425 U5.38@20.975,26.425 ; FB3.1@25.633,68.3 25.733,68.4 v7(26.1,68.4) ; v7(26,67.7) 26,67.033 R61.1@26.1,66.933 ; R6.1@26.233,69.2 26.233,69.208 26.626,69.6 v7(27,69.6) ; v7(29.8,50.7) U1.48@29.8,52.9 ; U8.4@38.975,18.55 v1(38.975,20.625) ; U7.4@46.575,20.45 v1(48.675,20.45) ; U6.4@50.25,17.2 51.4,17.2 52.392,17.2 v1(52.8,17.608) ; v6(57.853,25.401) 57.853,26.026 57.85,26.029 57.85,27.35 57.879,27.35 U3.8@58.879,28.35 U3.8@58.9,28.371 ; v6(68.6,60.1) 69.513,60.1 P3.1@69.55,60.137
  Top Layer w0.8: C22.1@53.8,87.175 55.025,87.175 56.4,88.55 56.4,90.1 57.6,91.3
  Top Layer w1: R1.1@1,70.589 1.469,70.12 J5.3@3.3,70.12
  other v7: 34,66.875 34.875,66.875 33.575,67.575 34.4,67.575 35.225,67.575 2.5,69.2 4,69.2 3.3,71.3 52.975,86.625 53.8,86.625 54.625,86.625
3V3OUT: C103.1 U13.10 | length 0.8
  Top Layer w0.3: U13.10@23.275,74.575 C103.1@23.275,75.4
ADC: D38.1 J12.6 U5.39 | length 40.3
  Top Layer w0.3: J12.6@3.2,34.2 D38.1@4.994,34.2 ; v1(18.6,28.7) 18.6,27.396 20.071,25.925 U5.39@20.975,25.925
  Routing w0.2: J12.6@3.2,34.2 1.5,32.5 1.5,23.3 2.6,22.2 6.2,22.2 6.9,22.9 6.9,25.625 9.275,28 11.9,28 12.6,28.7 14.5,28.7 15.45,29.65 17.65,29.65 v1(18.6,28.7)
AGD: C63.1 C64.1 U5.42 | length 3.7
  Top Layer w0.3: C63.1@18.07,25.4 18.07,24.8 18.6,24.8 18.975,24.425 U5.42@20.975,24.425
ANT1: D16.2 R82.2 TP14.1 | length 2
  Top Layer w0.33: D16.2@58.4,1.72 TP14.1@58.4,2.767 R82.2@58.4,3.767
ANT1_LED: R82.1 U1.28 | length 77.6
  Top Layer w0.2: U1.28@20.15,57.05 v1(21.15,57.05)
  Top Layer w0.3: R82.1@58.4,4.833 v1(58.4,5.4)
  Routing w0.2: v1@20.95,57.05 v1(21.15,57.05) 24.75,57.05 29.122,52.678 32.522,52.678 35.3,49.9 35.3,46.225 37.1,44.425 37.1,37.675 39.5,35.275 39.5,29.6 41.7,27.4 47.6,27.4 48.25,26.75 48.25,24.05 54.279,18.021 55.979,18.021 58.55,15.45 58.55,6.682 58.5,6.632 58.5,6.218 58.55,6.168 58.55,5.55 v1(58.4,5.4)
ANT2: D17.2 R83.2 TP15.1 | length 2.1
  Top Layer w0.33: D17.2@63.561,1.713 TP15.1@63.561,2.7 R83.2@63.561,3.767
ANT2_LED: R83.1 U1.27 | length 84.7
  Top Layer w0.2: U1.27@20.15,57.55 v1(21.8,57.55)
  Top Layer w0.3: R83.1@63.6,4.833 v1@63.6,5.4
  Routing w0.2: v1(21.8,57.55) 24.85,57.55 29.322,53.078 33.022,53.078 38.5,47.6 38.5,38.125 39.725,36.9 39.725,35.925 40,35.65 40,29.9 42,27.9 52,27.9 53.5,26.4 53.5,19.4 53.855,19.045 56.655,19.045 58.805,16.895 58.805,16.341 58.95,16.196 58.95,7.35 60.9,5.4 v1(63.561,5.4) ; v1@63.561,5.439 v1@63.6,5.4
BLC_UART_CTS: R75.2 U1.44 | length 49
  Top Layer w0.2: U1.44@27.65,53.05 27.65,55.05 v1(28.8,56.2) ; v1(59.2,80.5) R75.2@59.2,83.267
  Routing w0.2: v1(28.8,56.2) 31.512,58.912 31.512,61.537 33.05,63.075 34.225,63.075 34.925,62.375 38.675,62.375 55.9,79.6 57.4,79.6 58.3,80.5 v1(59.2,80.5)
BLC_UART_RTS: R76.2 U1.45 | length 49
  Top Layer w0.2: U1.45@28.15,53.05 28.15,54.35 v1(29.5,55.7) ; v1(58.25,81.625) R76.2@58.25,83.292
  Routing w0.2: v1(29.5,55.7) 29.5,56.3 34.8,61.6 35.374,61.6 35.849,61.125 38.025,61.125 55.8,78.9 58.7,78.9 60.05,80.25 60.05,80.675 59.1,81.625 v1(58.25,81.625)
BLC_UART_RX: R72.2 U1.59 | length 40.6
  Top Layer w0.2: U1.59@31.65,60.05 34.117,60.05 v1(35.167,61.1) ; v1(61.05,80.55) 61.1,80.6 R72.2@61.1,82.917
  Routing w0.2: v1(35.167,61.1) 35.567,60.7 38.2,60.7 55.9,78.4 58.9,78.4 v1(61.05,80.55)
BLC_UART_TX: R73.2 U1.58 | length 43.5
  Top Layer w0.2: U1.58@31.65,59.55 34.35,59.55 34.7,59.9 v1(35,59.9) ; v1(60.125,81.5) R73.2@60.125,83.267
  Routing w0.2: v1(35,59.9) 35.325,60.225 38.325,60.225 55.9,77.8 59.55,77.8 61.95,80.2 61.95,81 61.45,81.5 v1(60.125,81.5)
BOOT0: D10.1 D15.1 R37.2 | length 4
  Top Layer w0.3: D15.1@32.78,63.4 33.78,64.4 R37.2@33.933,64.4 34.975,64.4 35.5,64.925 D10.1@36.1,64.925
BT_OK: R77.1 U12.1 | length 3.9
  Top Layer w0.3: R77.1@72.712,83.333 73.833,83.333 74.3,83.8 U12.1@74.3,85.9
CBIB: C88.1 C89.1 U5.9 | length 2.4
  Top Layer w0.25: U5.9@25.4,20.875 25.4,18.545 C89.1@25.475,18.47
CBV: C83.1 C84.1 U5.8 | length 2.4
  Top Layer w0.25: C84.1@24.975,18.54 U5.8@24.975,20.925
CD1: C61.1 C62.1 U5.41 | length 4
  Top Layer w0.3: C61.1@18.07,26.6 18.07,26 18.3,26 19.375,24.925 U5.41@20.975,24.925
